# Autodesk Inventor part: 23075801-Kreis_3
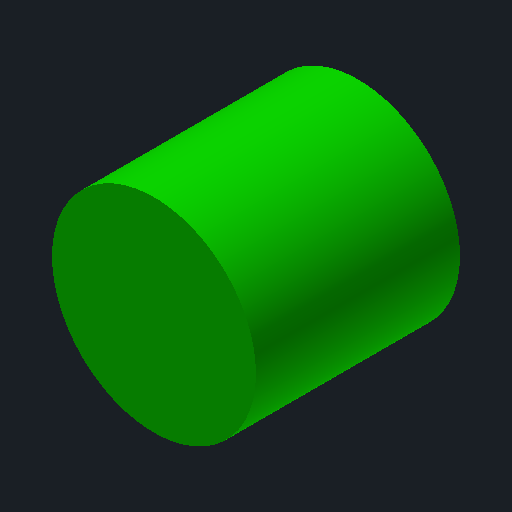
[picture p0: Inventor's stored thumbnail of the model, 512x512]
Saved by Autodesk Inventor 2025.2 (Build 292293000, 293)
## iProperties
Company: Ed. Züblin AG
Created: 2025-03
Part Number: 23075801-Kreis_3
Material: Stahlbeton C30/37
Document SubType Name: Modeling
Designer: FrodlSte
Mass: 1.9635e+06 g
Surface Area: 47123.9 cm^2
Volume: 785398 cm^3
Density: 2.5 g/cm^3
Appearance: Beton C30/37
Description: Abdichtungstraeger
z_Bereich: Tunnelbau
z_Direktion: Tief- und Tunnelbau
z_Konzerneinheit: Zentrale Technik
z_Matchkey: =<z_Matchkey_010>_<z_Matchkey_020>_<z_Matchkey_030>_<z_Matchkey_040>_<z_Matchkey_050>_<z_Matchkey_060>_<z_Matchkey_070>_<z_Matchkey_080>_<z_Matchkey_090>_<z_Mat
cpiComponentType: Attribut
cpiFitMatchkey: =<z_Matchkey>
z_Matchkey_010: xxxxx
z_Matchkey_020: 5DTUB
z_Matchkey_030: xxx
z_Matchkey_040: xxx
z_Matchkey_050: xxx
z_Matchkey_060: xxx
z_Matchkey_070: xxx
z_Matchkey_080: xxx
z_Matchkey_090: xxx
z_Matchkey_100: xxx
z_Matchkey_110: xxx
z_Matchkey_120: xxxxxxx
z_Matchkey_130: KALO
z_Matchkey_140: LAIB
DocNumber: 23075801-Kreis_3.ipt
Folder: DL23075801-DE-Pfaffensteigtunnel\BIM\Testmodell
VDS_Category: 09 - BIM - Konstruktion
DBSet_Beton:Betondeckung_mm: -9999,900000000001
DBSet_Beton:Betonstahlguete: BST_500A
DBSet_Beton:Bewehrungsgehalt: -99999.0
DBSet_Beton:Druckfestigkeitsklasse: C12/15
DBSet_Beton:Expositionsklasse_X: ND
DBSet_Beton:Expositionsklasse_XA: ND
DBSet_Beton:Expositionsklasse_XC: ND
DBSet_Beton:Expositionsklasse_XD: ND
DBSet_Beton:Expositionsklasse_XF: ND
DBSet_Beton:Expositionsklasse_XM: ND
DBSet_Beton:Expositionsklasse_XS: ND
DBSet_Beton:Feuchtigkeitsklasse: ND
DBSet_Beton:Groesstkorn: 11
DBSet_Beton:Herstellungsort: FTB
DBSet_Beton:Luftporenbeton: ND
DBSet_Beton:PP_Faser: False
DBSet_Beton:PP_Faser_Gehalt: -99999.0
DBSet_Beton:Rohdichte: -99999.0
DBSet_Beton:Sichtbetonklasse: ND
DBSet_Beton:Unbewehrter_Beton: False
DBSet_Beton:Wasserzementwert_max: -99999.0
DBSet_Beton:WU_Beton: ND
DBSet_Beton:Zusatzmittel: ND
DBSet_Element:010_Eigentuemer: DBE
DBSet_Element:020_Autor: ND
DBSet_Element:030_Projektnummer: G.016268527
DBSet_Element:040_Bereich: ND
DBSet_Element:050_Vertragspartner: ND
DBSet_Element:060_Gewerk: ND
DBSet_Element:070_Bauwerk: EW
DBSet_Element:080_Bauwerksnummer: 17030
DBSet_Element:090_Bezeichnung: ND
DBSet_Element:100_Gruppe: Abdichtung
DBSet_Element:110_Element: Abdichtungstraeger
DBSet_Element:120_Elementtyp: ND
DBSet_Element:130_Identifikationsnummer: ND
DBSet_Element:140_Position_1: KALO
DBSet_Element:150_Position_2: FIRS
DBSet_Element:160_PUID: ND
DBSet_Element:170_Hauptmaterialitaet: Baugrund
DBSet_Element:171_Materialindikator_1: ND
DBSet_Element:172_Materialindikator_2: ND
DBSet_Geometrie:Dicke: -99999.0
DBSet_Geometrie:Flaeche: -99999.0
DBSet_Geometrie:Volumen_Solid: 7.21
DBSet_Position:Streckenachse: ND
DBSet_Position:Streckenkilometer_Anfang: -99999
DBSet_Position:Streckenkilometer_Ende: -99999
DBSet_Position:Tunnelachse: ND
DBSet_Position:Tunnelmeter_Anfang: -99999
DBSet_Position:Tunnelmeter_Ende: -99999
DBSet_TP:Status: ABB
z_DBSet_Geometrie:Flaeche: -99999,000 m^2
z_DBSet_Beton:Betondeckung_mm: -99999,000 mm
z_DBSet_Beton:Betonstahlguete: Nicht definiert
z_DBSet_Beton:Bewehrungsgehalt: -99999,000 oE
z_DBSet_Beton:Druckfestigkeitsklasse: Beton C25/30
z_DBSet_Beton:Expositionsklasse_X: Nicht definiert
z_DBSet_Beton:Expositionsklasse_XA: Nicht definiert
z_DBSet_Beton:Expositionsklasse_XC: Nicht definiert
z_DBSet_Beton:Expositionsklasse_XD: Nicht definiert
z_DBSet_Beton:Expositionsklasse_XF: Nicht definiert
z_DBSet_Beton:Expositionsklasse_XM: Nicht definiert
z_DBSet_Beton:Expositionsklasse_XS: Nicht definiert
z_DBSet_Beton:Feuchtigkeitsklasse: Nicht definiert
z_DBSet_Beton:Groesstkorn: 8 mm
z_DBSet_Beton:Herstellungsort: Spritzbeton
z_DBSet_Beton:Luftporenbeton: nicht definiert
z_DBSet_Beton:PP_Faser: Falsch
z_DBSet_Beton:PP_Faser_Gehalt: -99999,000 oE
z_DBSet_Beton:Rohdichte: -99999,000 oE
z_DBSet_Beton:Sichtbetonklasse: Nicht definiert
z_DBSet_Beton:Unbewehrter_Beton: Wahr
z_DBSet_Beton:Wasserzementwert_max: -99999,000 oE
z_DBSet_Beton:WU_Beton: False
z_DBSet_Beton:Zusatzmittel: nicht definiert
z_DBSet_Element:010_Eigentuemer: DBInfraGo
z_DBSet_Element:020_Autor: Vertragspartner 2 ZB
z_DBSet_Element:030_Projektnummer: Gaeubahn Nord HP Goldberg (DBnfraGO, BK11)
z_DBSet_Element:040_Bereich: PFA 1 Tunnel
z_DBSet_Element:050_Vertragspartner: Tunnel
z_DBSet_Element:060_Gewerk: Tunnelbau
z_DBSet_Element:070_Bauwerk: SBW-Tu
z_DBSet_Element:080_Bauwerksnummer: zzz (leer)
z_DBSet_Element:090_Bezeichnung: zzz (leer)
z_DBSet_Element:100_Gruppe: Abdichtung
z_DBSet_Element:110_Element: Abdichtungstraeger
z_DBSet_Element:120_Elementtyp: Abdichtungstraeger
z_DBSet_Element:130_Identifikationsnummer: Nicht definiert
z_DBSet_Element:140_Position_1: Kalotte
z_DBSet_Element:150_Position_2: Nicht definiert
z_DBSet_Element:160_PUID: Nicht definiert
z_DBSet_Element:170_Hauptmaterialitaet: Beton
z_DBSet_Element:171_Materialindikator_1: Spritzbeton
z_DBSet_Element:172_Materialindikator_2: Nicht definiert
z_DBSet_Geometrie:Dicke: 0,020 m
z_DBSet_Position:Streckenachse: zzz (leer)
z_DBSet_Position:Streckenkilometer_Anfang: -11111,000 oE
z_DBSet_Position:Streckenkilometer_Ende: -11111,000 oE
z_DBSet_Position:Tunnelachse: zzz (leer)
z_DBSet_Position:Tunnelmeter_Anfang: -11111,000 oE
z_DBSet_Position:Tunnelmeter_Ende: -11111,000 oE
z_DBSet_TP:Status: Neubau
z_DBSet_Geometrie:Volumen_Solid: -11111,000 m^3
Author: FrodlSte
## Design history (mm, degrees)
derived "23075801-Skelett.ipt"
node "Kreis_3"
node "Volumenkörpern"
node "Oberflächenkörpern"
feature "Kreis_3::23075801-Skelett.ipt" dims "d4" = 10
tag "Bezeichnung1"
